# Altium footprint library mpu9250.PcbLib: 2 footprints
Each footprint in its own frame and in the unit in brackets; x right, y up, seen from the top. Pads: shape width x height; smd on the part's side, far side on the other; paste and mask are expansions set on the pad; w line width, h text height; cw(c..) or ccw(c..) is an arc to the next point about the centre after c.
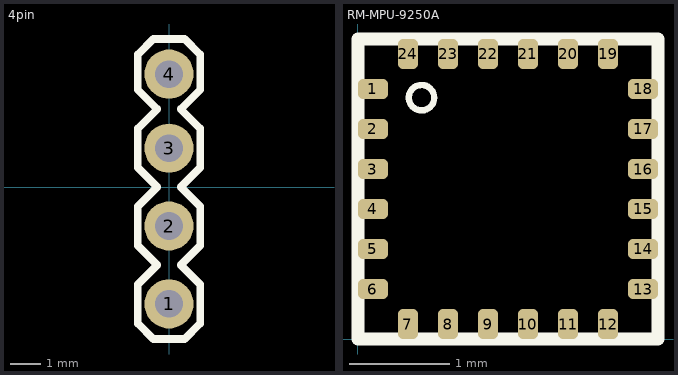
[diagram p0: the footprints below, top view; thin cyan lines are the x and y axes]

## 4pin [mm]
pads (4):
  round 1.6 hole 0.9: 1(0,-3.81) 2(0,-1.27) 3(0,1.27) 4(0,3.683)
Top Overlay:
  lines w0.254: -1.016,-4.445 -0.508,-4.953 0.508,-4.953 1.016,-4.445 1.016,-3.175 0.381,-2.54 1.016,-1.905 1.016,-0.635 0.381,0 1.016,0.635 1.016,1.905 0.381,2.54 1.016,3.175 1.016,4.318 0.508,4.826 -0.508,4.826 -1.016,4.318 -1.016,3.175 -0.381,2.54 -1.016,1.905 -1.016,0.635 -0.381,0 -1.016,-0.635 -1.016,-1.905 -0.381,-2.54 -1.016,-3.175 -1.016,-4.445

## RM-MPU-9250A [mm]
pads (24):
  rrect50% 0.3x0.2 smd mask+0.05: 1(0.15,2.5) 2(0.15,2.1) 3(0.15,1.7) 4(0.15,1.3) 5(0.15,0.9) 6(0.15,0.5) 13(2.85,0.5) 14(2.85,0.9) 15(2.85,1.3) 16(2.85,1.7) 17(2.85,2.1) 18(2.85,2.5)
  rrect50% 0.2x0.3 smd mask+0.05: 7(0.5,0.15) 8(0.9,0.15) 9(1.3,0.15) 10(1.7,0.15) 11(2.1,0.15) 12(2.5,0.15) 19(2.5,2.85) 20(2.1,2.85) 21(1.7,2.85) 22(1.3,2.85) 23(0.9,2.85) 24(0.5,2.85)
Top Overlay:
  circle w0.064: c0.635,2.413 r0.127
  lines w0.127: 0,0 3,0 3,3 0,3 0,0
